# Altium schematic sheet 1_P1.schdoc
size 307 x 218 mm; Symbol: Drawing-Symbol_A4; Device: Drawing-Symbol_A4; @Project Name: New Project_2026-05-19_11-50-23; @Page Count: 1; @Update Date: 2026-05-27; @Create Date: 2026-05-19; @Schematic Name: JANELINK-ESP32; @Page No: 1; @Page Name: P1; Company: EasyEDA.com; Version: V1.0; Page Size: A4; @Create Time: 11:50:32; @Update Time: 21:31:37; Width: 1170; Height: 825; Region Start: 1; X Region Count: 6; Y Region Count: 4; Blade Width: 10; Title Block Position: 3; @Board Name: Board1
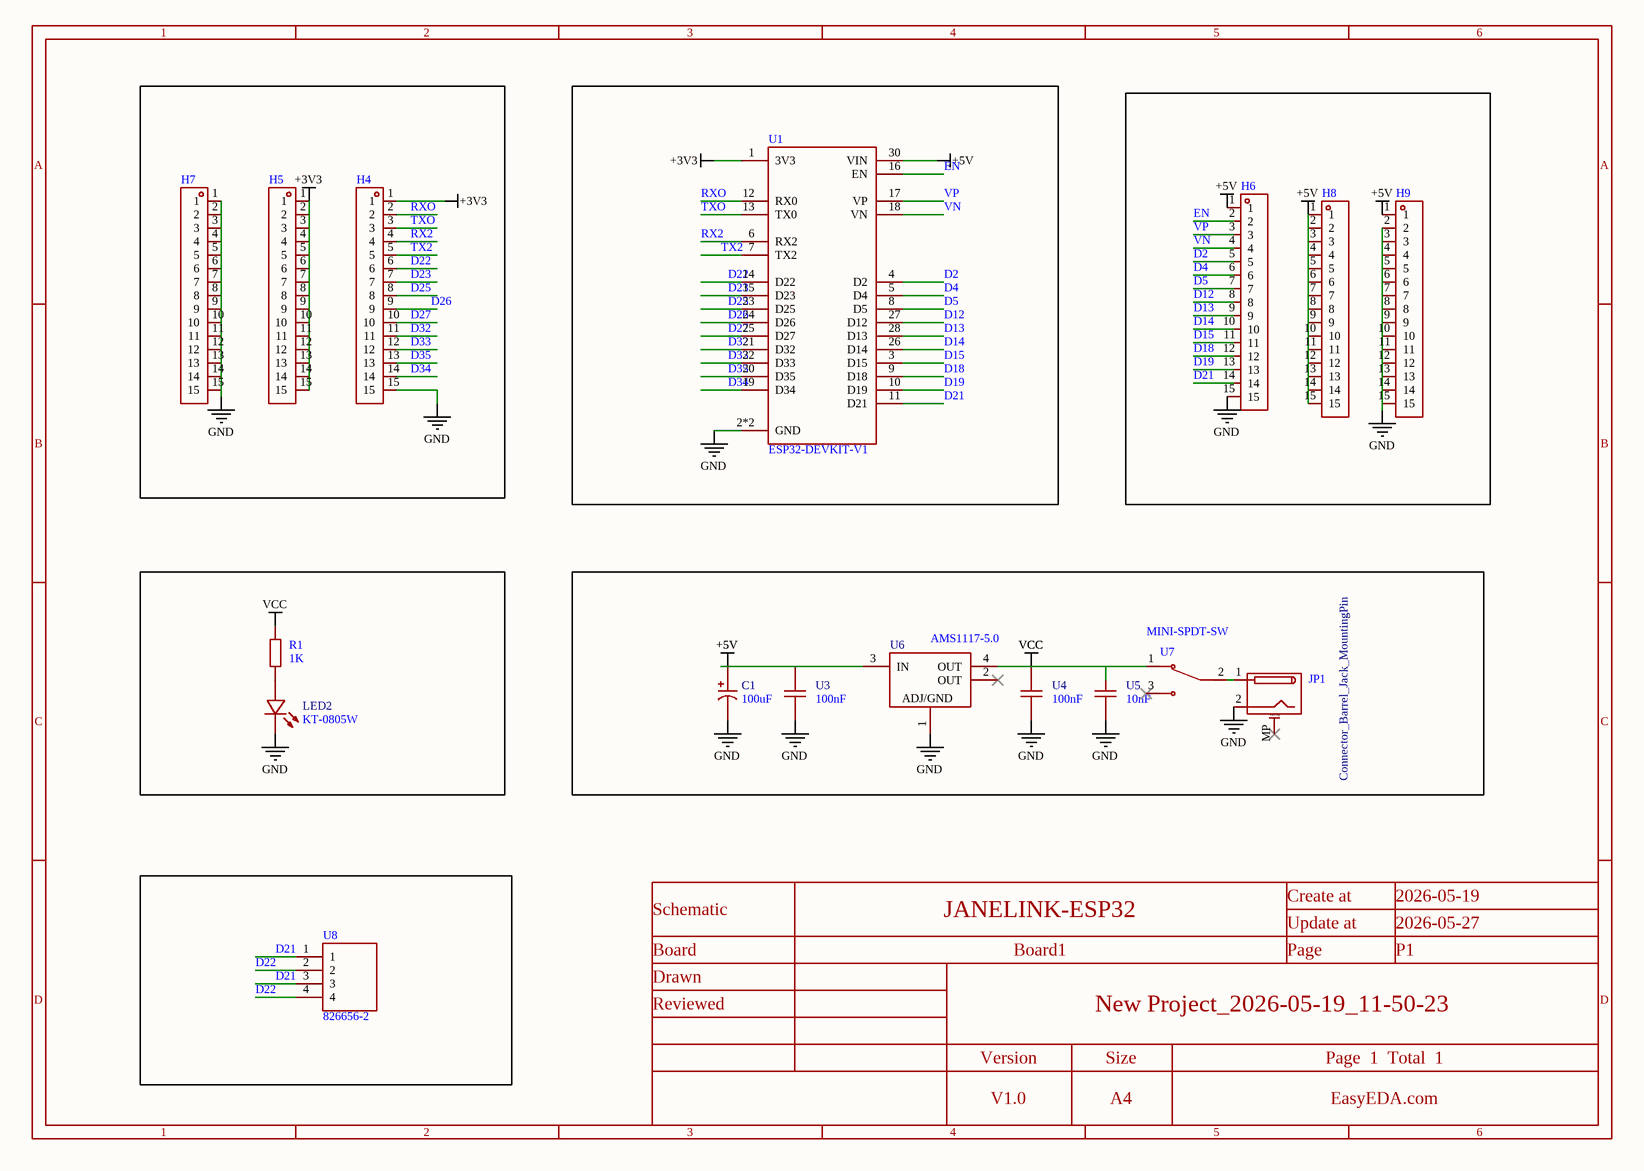
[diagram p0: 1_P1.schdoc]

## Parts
C1  100uF  [CAP-TH_BD8.0-P3.50-D0.6-FD_1]
H4  (no value)  [HDR-TH_15P-P2.54-V-M]
H5  (no value)  [HDR-TH_15P-P2.54-V-M]
H6  (no value)  [HDR-TH_15P-P2.54-V-M]
H7  (no value)  [HDR-TH_15P-P2.54-V-M]
H8  (no value)  [HDR-TH_15P-P2.54-V-M]
H9  (no value)  [HDR-TH_15P-P2.54-V-M]
JP1  Connector_Barrel_Jack_MountingPin  [Connector_BarrelJack:BarrelJack_Wuerth_6941xx301002]
LED2  KT-0805W  [LED0805-R-RD]
R1  1K  [R0603]
U1  ESP32-DEVKIT-V1  [MODULE_ESP32_DEVKIT_V1]
U3  100nF  [CAP-TH_L5.0-W2.5-P5.00-D1.0]
U4  100nF  [CAP-TH_L5.0-W2.5-P5.00-D1.0]
U5  10nF  [C1206]
U6  AMS1117-5.0  [SOT-223-3_L6.4-W3.5-P2.30-LS7.0-BR]
U7  MINI-SPDT-SW  [SW_MINI-SPDT-SW]
U8  826656-2  [TE_826656-2]

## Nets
+3V3: H4.1 H5.1 H5.2 H5.3 H5.4 H5.5 H5.6 H5.7 H5.8 H5.9 H5.10 H5.11 H5.12 H5.13 H5.14 H5.15 U1.1(3V3)
+5V: C1.1 H6.1 H8.1 H8.2 H8.3 H8.4 H8.5 H8.6 H8.7 H8.8 H8.9 H8.10 H8.11 H8.12 H8.13 H8.14 H8.15 H9.1 U1.30(VIN) U3.1 U6.3(IN)
GND: C1.2 H4.15 H6.15 H7.1 H7.2 H7.3 H7.4 H7.5 H7.6 H7.7 H7.8 H7.9 H7.10 H7.11 H7.12 H7.13 H7.14 H7.15 H9.2 H9.3 H9.4 H9.5 H9.6 H9.7 H9.8 H9.9 H9.10 H9.11 H9.12 H9.13 H9.14 H9.15 JP1.2 LED2.2(K) U1.2*2(GND) U3.2 U4.2 U5.1 U6.1(ADJ/GND)
VCC: R1.2 U4.1 U5.2 U6.4(OUT) U7.1
D2: H6.5 U1.4(D2)
D4: H6.6 U1.5(D4)
D5: H6.7 U1.8(D5)
D12: H6.8 U1.27(D12)
D13: H6.9 U1.28(D13)
D14: H6.10 U1.26(D14)
D15: H6.11 U1.3(D15)
D18: H6.12 U1.9(D18)
D19: H6.13 U1.10(D19)
D21: H6.14 U1.11(D21) U8.1 U8.3
D22: H4.6 U1.14(D22) U8.2 U8.4
D23: H4.7 U1.15(D23)
D25: H4.8 U1.23(D25)
D26: H4.9 U1.24(D26)
D27: H4.10 U1.25(D27)
D32: H4.11 U1.21(D32)
D33: H4.12 U1.22(D33)
D34: H4.14 U1.19(D34)
D35: H4.13 U1.20(D35)
EN: H6.2 U1.16(EN)
RX2: H4.4 U1.6(RX2)
RXO: H4.2 U1.12(RX0)
TX2: H4.5 U1.7(TX2)
TXO: H4.3 U1.13(TX0)
VN: H6.4 U1.18(VN)
VP: H6.3 U1.17(VP)
NetJP1_1: JP1.1 U7.2
NetLED2_1: LED2.1(A) R1.1

Not connected (* = marked no-connect by the designer): JP1 MP(MountPin)*; U6 2(OUT)*; U7 3*

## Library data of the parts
C1 = 100uF: Symbol: 100UF_C9900016884; Add into BOM: yes
H4-H9 = HDR-M_2.54_1x15P: Symbol: HDR_2.54-1x15P; Convert to PCB: yes
JP1 = Connector_Barrel_Jack_MountingPin: Users: REF**; ki_fp_filters: BarrelJack*; Add into BOM: yes
LED2 = KT-0805W: Manufacturer: KENTO; Symbol: whiteLEDSMD; Add into BOM: yes; Lamp Holder Type: 2mm x 1.25mm square LED; Illumination Color: White; Voltage - Forward(Vf): 2.6V~3.2V; Power(Watts): 80mW; Forward Current: 25mA; Diode Configuration: Discrete Diode; Lens Color: Yellow Lens; Color Temperature: 13172K~100000K; Luminous Intensity: 350mcd; Viewing Angle: 120°
R1 = Res_0603: Symbol: Res; Convert to PCB: yes; Value: 10K
U1 = ESP32-DEVKIT-V1: Add into BOM: yes
U3 U4 = 100nF: Symbol: 100NF_C9900015256; Add into BOM: yes
U5 = 10nF: Add into BOM: yes
U6 = AMS1117-5.0: Manufacturer: 国芯佳品; Symbol: AMS1117-5.0_C2992571; Add into BOM: yes; Output Type: Fixed; Voltage - Supply: 15V; Output Voltage: 5V; Output Current: 1A; Voltage Dropout: 1.3V@(1A); standby current: 4mA; Output Configuration: Positive; Number of Outputs: 1
U7 = MINI-SPDT-SW: Add into BOM: yes
U8 = pin_2x2: Add into BOM: yes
